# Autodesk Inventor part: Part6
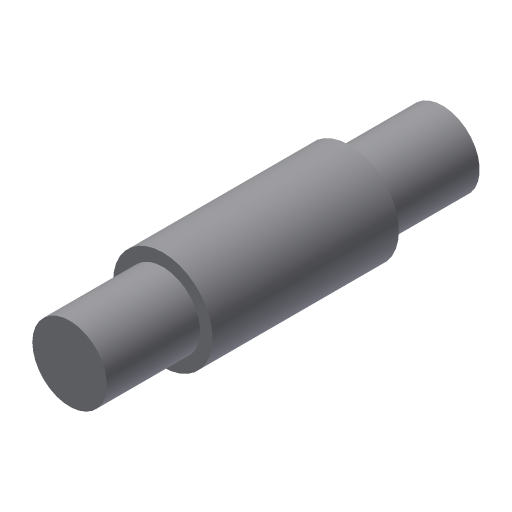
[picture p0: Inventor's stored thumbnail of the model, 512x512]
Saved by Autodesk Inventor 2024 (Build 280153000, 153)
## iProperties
Shininess: 77.0
Length Units: 11269
Angle Units: 11279
Time Units: 11290
Mass Units: 11283
Length Display Precision: 3
Angle Display Precision: 2
Created: 2002-01
Part Number: Part6
Document SubType Name: Modeling
Designer: ***
Density: 1 g/cm^3
Material: Generic
Appearance: Default
Density: 0.0
Volumn: 0.0
Area: 0.0
PropertySet Name: Model Information
Control State: 0
Master: False
Checked Out: False
Author: ***
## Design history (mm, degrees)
sketch "Sketch1"
  geometry: L1 (1.545, 32.521)-(-4.455, 32.521); L2 (-4.455, 32.521)-(-4.455, 17.521); L3 (-4.455, 17.521)-(-6.455, 17.521); L4 (-6.455, 17.521)-(-6.455, -12.479); L5 (-6.455, -12.479)-(-4.455, -12.479); L6 (-4.455, -12.479)-(-4.455, -27.479); L7 (-4.455, -27.479)-(1.545, -27.479); L8 (1.545, -27.479)-(1.545, 32.521)
  constraints: 16 end point, 5 parallel, 2 equal length, 1 collinear, 1 horizontal, 1 perpendicular
  dimensions: "d0" = 16 diameter of L4 L8; "d1" = 12 diameter of L2 L8; "d2" = 60 distance of L7.end L1.start; "d3" = 30 distance of L3.end L4.end
revolve "Revolution1" sketch "Sketch1" stored, may be unused: angle "d4" = 90 deg
body "Solid1"
